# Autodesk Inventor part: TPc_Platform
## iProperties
Shininess: 64.0
Length Units: 11272
Angle Units: 11279
Time Units: 11290
Mass Units: 11286
Length Display Precision: 3
Angle Display Precision: 2
Compacted: True
Part Number: TPc_Platform
Document SubType Name: Modeling
Created: 2004-08
Designer: John Blackburn
Material: Aluminum-6061
Manufacturer: Standard
Standards Organization: Custom
Density: 0.0
Volumn: 0.0
Area: 0.0
PropertySet Name: Model Information
Control State: 0
Master: False
Checked Out: False
Author: John Blackburn
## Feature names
1. Extrusion1
